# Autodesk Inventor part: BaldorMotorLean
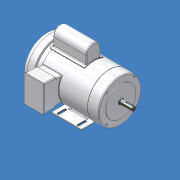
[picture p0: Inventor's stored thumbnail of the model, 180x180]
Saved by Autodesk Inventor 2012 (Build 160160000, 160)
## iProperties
Shininess: 64.0
Length Units: 11272
Angle Units: 11279
Time Units: 11290
Mass Units: 11286
Length Display Precision: 3
Angle Display Precision: 2
Compacted: True
Part Number: BaldorMotorLean
Document SubType Name: Modeling
Created: 2003-11
Designer: Larry Caldwell
Material: Steel CRS
Manufacturer: Standard
Standards Organization: Custom
Description: 3/4 Hp 56C
Density: 7.86 g/cm^3
Density: 0.0
Volumn: 0.0
Area: 0.0
PropertySet Name: Model Information
Control State: 0
Master: False
Checked Out: False
d55: 0.060 in
SaveDate: 2003-11-22
SaveTime: 10:54
TotalMass: 125.145 lbmass
TotalVolume: 440.714 in^3
Author: Larry Caldwell
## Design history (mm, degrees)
sketch "Sketch1"
  geometry: L1 (-114.18, 0)-(222.37, 0); L2 (-95.13, 91.313)-(-71.318, 91.313); L3 (-71.318, 91.313)-(-71.318, 0); L4 (-114.18, 0)-(-114.18, 72.263); L5 (-71.318, 82.55)-(-55.443, 83.104); L6 (-55.443, 83.104)-(128.009, 83.104); L7 (-54.681, 50.8)-(18.344, 50.8); L8 (18.344, 50.8)-(18.344, -50.8); L9 (18.344, -50.8)-(-54.681, -50.8); L10 (-54.681, -50.8)-(-54.681, 50.8); L11 (-18.168, 50.8)-(-18.168, -50.8); L12 (128.771, 83.104)-(170.046, 81.663); L13 (170.046, 81.663)-(170.046, 0); L14 (170.046, 57.15)-(173.094, 57.15); L15 (173.094, 57.15)-(173.094, 10.477); L16 (176.904, 7.938)-(221.608, 7.938); L17 (221.608, 7.938)-(222.37, 7.176); L18 (222.37, 7.176)-(222.37, 0); L19 (174.618, 10.223)-(170.046, 10.223); L20 (-71.318, 82.55)-(-84.018, 82.55); L21 (-84.018, 82.55)-(-84.018, 0); L22 (170.046, 10.477)-(173.094, 10.477); L23 (222.37, 5.398)-(190.62, 5.398); L24 (128.771, 83.104)-(128.771, 81.58); L25 (128.771, 81.58)-(128.009, 81.58); L26 (128.009, 81.58)-(128.009, 83.104); A1 r 19.05 centre (-95.13, 72.263) between (-95.13, 91.313) and (-114.18, 72.263); A2 r 2.286 centre (176.904, 10.224) between (174.618, 10.223) and (176.904, 7.938); A3 r 6.35 centre (190.62, 11.748) between (185.54, 7.938) and (190.62, 5.398); 3 further points
  constraints: 54 end point, 11 perpendicular, 11 point on line, 7 parallel, 6 point on circle, 4 tangent, 3 centre point, 3 horizontal, 3 midpoint
  dimensions: "d0" = 182.626 diameter of L2 L1; "d1" = 42.8625 distance between parallel lines of L3 L4; "d2" = 19.05 radius of A1; "d3" = 15.875 horizontal distance of L5.start L5.end; "d4" = 178 deg angle of L6 L5; "d5" = 101.6 distance between parallel lines of L9 L7; "d6" = 165.1 diameter of L5.start L1; "d7" = 178 deg angle of L12 L6; "d8" = 114.3 diameter of L14 L1; "d9" = 135 deg angle of L17 L16; "d10" = 0.762 horizontal distance of L16.end L17.end; "d11" = 52.324 distance between parallel lines of L18 L13; "d12" = 3.048 distance between parallel lines of L15 L13; "d13" = 15.875 diameter of L16 L1; "d14" = 2.286 radius of A2; "d15" = 47.752 distance from line of L18 L19.start; "d16" = 20.447 diameter of L19 L1; "d17" = 336.55 distance between parallel lines of L18 L4; "d18" = 41.275 horizontal distance of L12.start L12.end; "d19" = 12.7 distance between parallel lines of L3 L21; "d20" = 0.254 distance between parallel lines of L22 L19; "d21" = 31.75 distance from line of L18 A3.centre; "d22" = 2.54 distance between parallel lines of L16 L23; "d23" = 6.35 radius of A3; "d24" = 0.762 distance between parallel lines of L26 L24; "d25" = 1.524 distance between parallel lines of L6 L25; "d26" = 166.20873 diameter of L12.start L1; "d27" = 96.012 distance between parallel lines of L11 L4; "d28" = 73.025 distance of L7.start L7.end; "d29" = 18.16803 distance from line of point (0, 0) L11; "d30" = 162.31316 distance from line of point (0, 0) L17; "d31" = 222.36997 distance from line of point (0, 0) L18
revolve "Revolution1" stored, may be unused: angle "d32" = 90 deg
revolve "Revolution2" stored, may be unused: angle "d33" = 90 deg
fillet "Fillet1" dims "d36" = 3.175
sketch "Sketch2"
  geometry: L1 (-35.304, -85.725)-(35.304, -85.725); L2 (0, -85.725)-(0, -92.71); L3 (0, 0)-(0, -85.725); C1 r 72.263 at (0, 0) reference; A1 r 92.71 centre (0, 0) between (-35.304, -85.725) and (35.304, -85.725)
  constraints: 6 end point, 3 point on circle, 1 centre point, 1 coincident, 1 collinear, 1 midpoint, 1 vertical
  dimensions: "d39" = 85.725 distance from line of C1.centre L1; "d40" = 92.71 radius of A1
extrude "Extrusion2" cut sketch "Sketch2" stored distance "d41" = 6.35; taper "d42" = 0 deg
fillet "Fillet2" dims "d43" = 3.175
workplane "Work Plane1"
sketch "Sketch3"
  geometry: L1 (0, 0)-(0, 83.104); L2 (0, 0)-(-45.213, 69.729); L3 (0, 0)-(45.213, 69.729); L4 (-45.213, 69.729)-(-46.038, 71.001); L5 (45.213, 69.729)-(46.038, 71.001); L6 (-50.8, 139.7)-(50.8, 139.7); L7 (44.752, 90.591)-(44.268, 72.118); L8 (-44.752, 90.591)-(-44.268, 72.118); L9 (-50.8, 139.7)-(-49.634, 95.167); L10 (50.8, 139.7)-(49.634, 95.167); L11 (-50.8, 141.986)-(50.8, 141.986); L12 (-50.8, 141.986)-(-52.388, 141.986); L13 (-52.388, 141.986)-(-52.388, 139.7); L14 (-50.8, 139.7)-(-52.388, 139.7); L15 (50.8, 139.7)-(52.388, 139.7); L16 (52.388, 139.7)-(52.388, 141.986); L17 (50.8, 141.986)-(52.388, 141.986); L18 (-46.46, 92.075)-(-46.275, 92.075); L19 (46.275, 92.075)-(46.46, 92.075); L20 (0, 0)-(0, 92.075); L21 (0, 92.075)-(0, 139.7); A1 r 83.104 centre (0, 0) between (0, 83.104) and (-45.213, 69.729); A2 r 84.621 centre (0, 0) between (46.038, 71.001) and (-46.038, 71.001); A3 r 3.175 centre (46.46, 95.25) between (46.46, 92.075) and (49.634, 95.167); A4 r 3.175 centre (-46.46, 95.25) between (-49.634, 95.167) and (-46.46, 92.075); A5 r 1.524 centre (-46.275, 90.551) between (-44.752, 90.591) and (-46.275, 92.075); A6 r 1.524 centre (46.275, 90.551) between (46.275, 92.075) and (44.752, 90.591); 2 further points
  constraints: 42 end point, 15 point on circle, 10 tangent, 7 perpendicular, 6 centre point, 5 collinear, 4 parallel, 4 point on line, 3 horizontal alignment, 2 equal length, 2 equal radius, 2 vertical alignment, 1 coincident with centre, 1 midpoint, 1 vertical
  dimensions: "d45" = 1.51625 radial gap between concentric circles of A2 A1 (= d55); "d46" = 92.075 distance of L5.end L4.end; "d48" = 101.6 distance of L6.start L6.end; "d51" = 3.175 radius of A3; "d52" = 19.95697 vertical distance of point (-44.79, 92.075) L8.end; "d56" = 84.62062 radius of A2; "d61" = 104.775 distance between parallel lines of L16 L13; "d62" = 2.286 distance between parallel lines of L11 L6; "d63" = 52.3875 distance from line of L21.end L13 (= 0.5 x d61); "d66" = 1.524 radius of A5; "d67" = 47.625 distance of L20.end L21.end; "d68" = 91.5 deg angle of L17 L10; "d69" = 88.5 deg angle of L17 L8; "d70" = 49.911 distance between parallel lines of L17 L19; "d71" = 4.76087 distance between parallel lines of L7 L10; "d72" = 1.5875 distance from line of L11.end L16
extrude "Extrusion3" join sketch "Sketch3" stored distance "d57" = 76.2; taper "d58" = 0 deg
extrude "Extrusion4" join sketch "Sketch3" stored distance "d59" = 73.025; taper "d60" = 0 deg
extrude "Extrusion5" join sketch "Sketch3" stored distance "d64" = 76.2; taper "d65" = 0 deg
fillet "Fillet3" dims "d73" = 3.175
fillet "Fillet4" dims "d74" = 1.524
workplane "Work Plane2"
sketch "Sketch4"
  geometry: L1 (0, 0)-(83.682, 0); L2 (0, 0)-(74.82, 36.17); L3 (0, 0)-(76.692, 35.762); L4 (0, 0)-(74.82, -36.17); L5 (0, 0)-(76.692, -35.762); L6 (74.82, 36.17)-(76.195, 36.81); L7 (76.692, 35.762)-(77.379, 36.083); L8 (76.692, -35.762)-(77.379, -36.083); L9 (74.82, -36.17)-(76.195, -36.81); L10 (112.713, 26.988)-(112.713, -26.988); L11 (81.001, -26.987)-(112.713, -26.988); L12 (81.001, 26.987)-(112.713, 26.988); A1 r 83.104 centre (0, 0) between (74.82, 36.17) and (74.82, -36.17); A2 r 85.379 centre (0, 0) between (77.379, -36.083) and (77.379, 36.083); A3 r 84.621 centre (0, 0) between (76.195, -36.81) and (76.692, 35.762); A4 r 84.621 centre (0, 0) between (76.692, 35.762) and (76.195, 36.81); A5 r 26.988 centre (112.713, 0) between (112.713, -26.988) and (112.713, 26.988); 1 further point
  constraints: 24 end point, 13 point on circle, 5 centre point, 4 parallel, 3 tangent, 2 coincident, 1 coincident with centre, 1 collinear, 1 horizontal, 1 perpendicular
  dimensions: "d76" = 166.20873 diameter of A1; "d77" = 25 deg angle of L3 L1; "d78" = 25.8 deg angle of L1 L2; "d79" = 170.75749 diameter of A2; "d80" = 25 deg angle of L5 L1; "d81" = 25.8 deg angle of L4 L1; "d82" = 84.62062 radius of A3; "d83" = 53.975 distance between parallel lines of L11 L12; "d84" = 26.9875 distance between parallel lines of L11 L1 (= 0.5 x d83); "d85" = 112.7125 distance from line of L1.start L10; "d86" = 29.0304 distance from line of L1.end L10
extrude "Extrusion6" join sketch "Sketch4" stored distance "d87" = 133.35; taper "d88" = 0 deg
extrude "Extrusion7" join sketch "Sketch4" stored distance "d89" = 130.175; taper "d90" = 0 deg
extrude "Extrusion8" join sketch "Sketch4" stored distance "d91" = 127; taper "d92" = 0 deg
fillet "Fillet5" dims "d93" = 3.175
fillet "Fillet6" dims "d94" = 3.175
sketch "Sketch5"
  geometry: L1 (104.775, -84.832)-(104.775, -88.007); L2 (104.775, -88.007)-(-9.525, -88.007); L3 (-9.525, -88.007)-(-9.525, -84.832); L4 (47.625, -88.007)-(47.625, -78.482); L5 (85.725, -88.007)-(85.725, -84.832); L6 (9.525, -88.007)-(9.525, -84.832); L7 (9.525, -86.419)-(85.725, -86.419); L8 (21.68, -78.482)-(73.57, -78.482); L9 (78.06, -80.341)-(81.62, -83.902); L10 (17.19, -80.341)-(13.63, -83.902); L11 (-9.525, -84.832)-(11.385, -84.832); L12 (83.865, -84.832)-(104.775, -84.832); L13 (11.385, -84.832)-(83.865, -84.832); L14 (-55.443, -83.104)-(128.009, -83.104) reference; A1 r 3.175 centre (11.385, -81.657) between (11.385, -84.832) and (13.63, -83.902); A2 r 3.175 centre (83.865, -81.657) between (81.62, -83.902) and (83.865, -84.832); A3 r 6.35 centre (21.68, -84.832) between (21.68, -78.482) and (17.19, -80.341); A4 r 6.35 centre (73.57, -84.832) between (78.06, -80.341) and (73.57, -78.482); 4 further points
  constraints: 26 end point, 11 tangent, 9 point on line, 8 point on circle, 6 parallel, 5 midpoint, 5 perpendicular, 4 centre point, 2 equal radius, 2 horizontal, 1 collinear
  dimensions: "d95" = 114.3 distance between parallel lines of L3 L1; "d96" = 76.2 distance between parallel lines of L5 L6; "d98" = 9.525 distance of L4.start L4.end; "d99" = 69.85 distance of point (82.55, -84.832) point (12.7, -84.832); "d100" = 135 deg angle of L8 L10; "d101" = 3.175 radius of A1; "d102" = 6.35 radius of A3; "d103" = 3.175 distance between parallel lines of L2 L11; "d105" = 47.625 distance from line of L4 point (0, 0); "d106" = 1.7272 distance between parallel lines of L14 L11
extrude "Extrusion9" join sketch "Sketch5" stored distance "d107" = 165.1; taper "d108" = 0 deg
extrude "Extrusion10" join sketch "Sketch5" stored distance "d109" = 76.2; taper "d110" = 0 deg
fillet "Fillet7" dims "d111" = 3.175
fillet "Fillet8" dims "d112" = 6.35
sketch "Sketch6"
  geometry: L1 (0, -165.1)-(114.3, -165.1) reference; L2 (114.3, -165.1)-(114.3, 0) reference; L3 (14.732, -33.274)-(14.732, -7.874); L4 (23.368, -7.874)-(23.368, -33.274); L5 (90.932, -33.274)-(90.932, -7.874); L6 (99.568, -7.874)-(99.568, -33.274); L7 (14.732, -157.526)-(14.732, -132.126); L8 (23.368, -132.126)-(23.368, -157.526); L9 (90.932, -157.526)-(90.932, -132.126); L10 (99.568, -132.126)-(99.568, -157.526); C1 r 4.318 at (19.05, -20.574); C2 r 4.318 at (95.25, -20.574); C3 r 4.318 at (19.05, -144.526); C4 r 4.318 at (95.25, -144.526); A1 r 4.318 centre (19.05, -33.274) between (14.732, -33.274) and (23.368, -33.274); A2 r 4.318 centre (19.05, -7.874) between (23.368, -7.874) and (14.732, -7.874); A3 r 4.318 centre (95.25, -7.874) between (99.568, -7.874) and (90.932, -7.874); A4 r 4.318 centre (95.25, -33.274) between (90.932, -33.274) and (99.568, -33.274); A5 r 4.318 centre (19.05, -132.126) between (23.368, -132.126) and (14.732, -132.126); A6 r 4.318 centre (19.05, -157.526) between (14.732, -157.526) and (23.368, -157.526); A7 r 4.318 centre (95.25, -157.526) between (90.932, -157.526) and (99.568, -157.526); A8 r 4.318 centre (95.25, -132.126) between (99.568, -132.126) and (90.932, -132.126); 2 further points
  constraints: 26 tangent, 16 end point, 16 point on circle, 12 centre point, 6 horizontal alignment, 4 parallel, 3 equal length, 3 equal radius, 2 midpoint, 2 vertical alignment
  dimensions: "d113" = 76.2 distance of C2.centre C1.centre; "d114" = 123.952 distance of C4.centre C2.centre; "d115" = 8.636 diameter of C1; "d116" = 25.4 distance of A1.centre A2.centre; "d117" = 19.05 distance from line of L2 C2.centre; "d118" = 20.574 distance from line of L1 C4.centre
extrude "Extrusion11" cut sketch "Sketch6" stored distance "d119" = 76.2; taper "d120" = 0 deg
sketch "Sketch7"
  geometry: L1 (-52.759, 52.759)-(52.759, 52.759); L2 (52.759, 52.759)-(52.759, -52.759); L3 (52.759, -52.759)-(-52.759, -52.759); L4 (-52.759, -52.759)-(-52.759, 52.759); C1 r 78.597 at (0, 0) reference; 1 further point
  constraints: 8 end point, 1 coincident, 1 horizontal, 7 other
  dimensions: "d122" = 149.225 distance of L2.end L1.start
hole "Hole1" sketch "Sketch7" at (-52.759, 52.759), (52.759, 52.759), (52.759, -52.759), (-52.759, -52.759) diameter "d123" = 7.7978; stored, may be unused: countersink angle "d127" = 82 deg, drill point angle "d129" = 118 deg; dims "d124" = 12.7, "d125" = 9.525, "d126" = 6.35, "d128" = 19.05
body "Solid1"
other parameters: "d44" = -18.161, "d47" = 92.075, "d49" = 47.625, "d50" = 88.5 deg, "d55" = 1.51625, "d75" = 22.225
